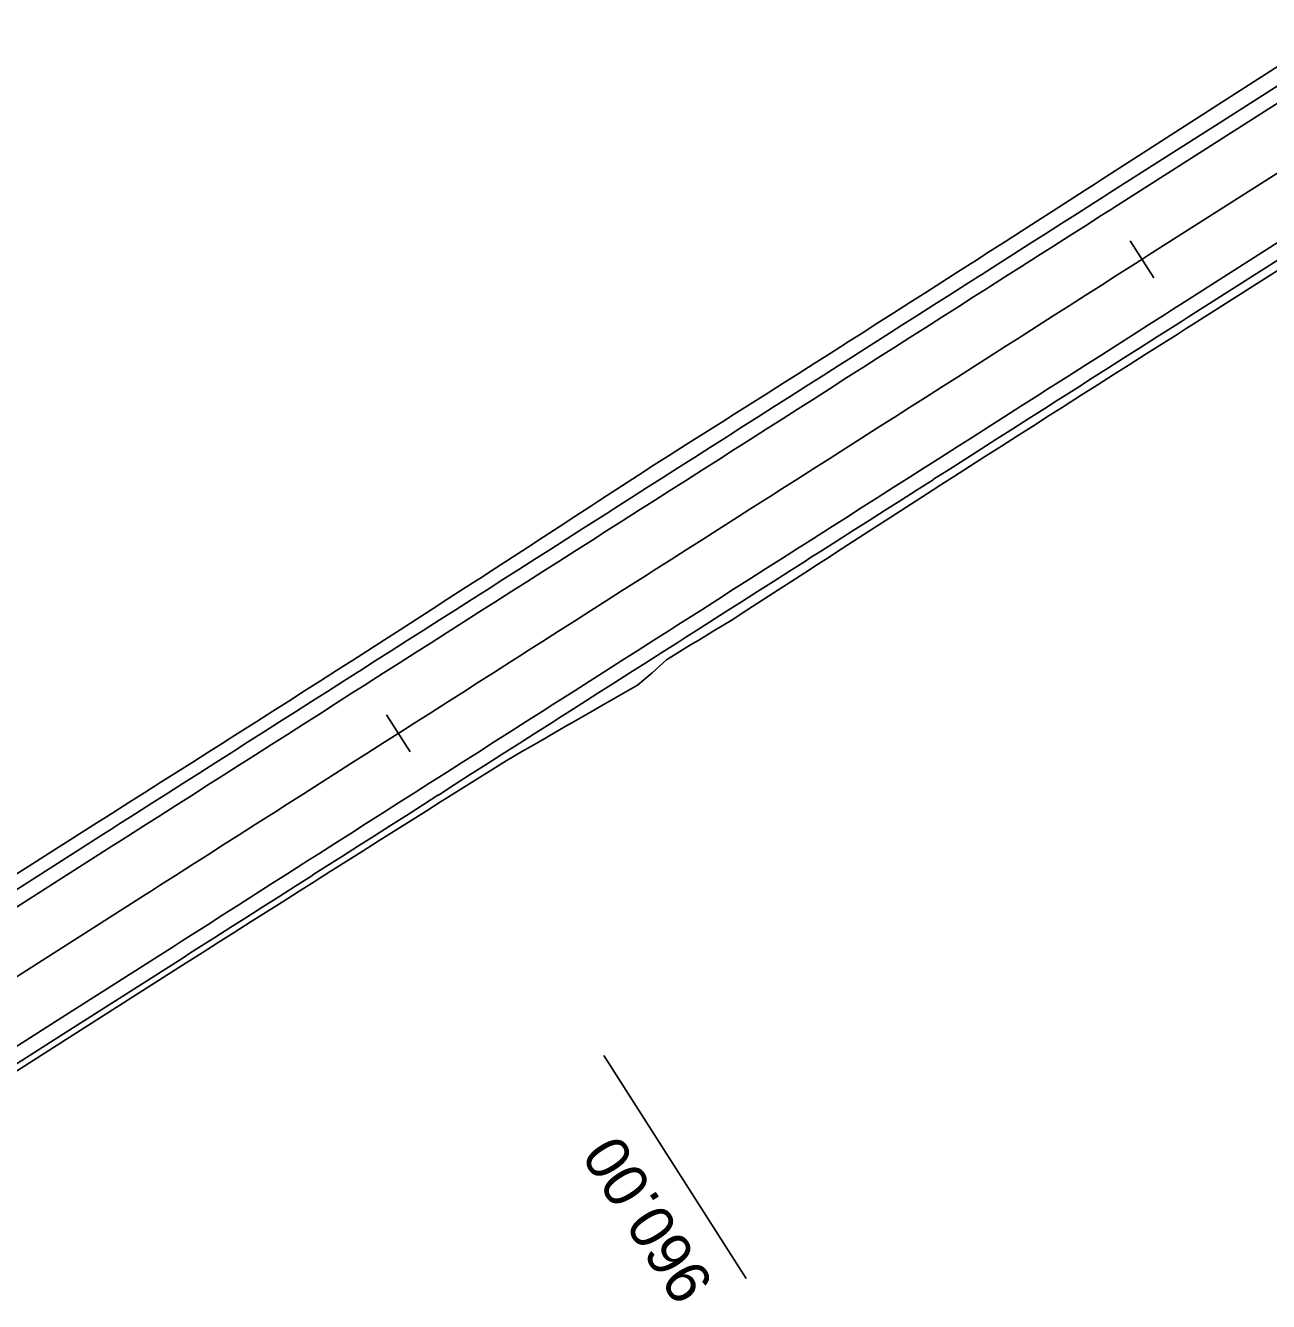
# Model space of a CAD drawing. Extents: x -550605 to -538780, y -1102367 to -1093705.
# Drawn here: x -547262.21 to -547219.93, y -1101213.61 to -1101170.2 of the extents above; entities that cross this region are included whole.
import ezdxf

# ---------------------------------------------------------------- set-up
doc = ezdxf.new("R2010")
doc.units = 0
for name, color, linetype in [('SIT - hrany vozovky', 7, 'Continuous'), ('SIT - osa cesty', 7, 'Continuous'), ('SIT - paty násypů', 7, 'Continuous'), ('SIT - staničení po 30m', 7, 'Continuous')]:
    doc.layers.add(name, color=color, linetype=linetype)

msp = doc.modelspace()

# ---------------------------------------------------------------- linework, layer by layer
at = {"layer": 'SIT - hrany vozovky'}
for points in [[(-547217.146, -1101170.672), (-547221.362, -1101173.36), (-547225.342, -1101175.897), (-547225.578, -1101176.048), (-547225.885, -1101176.243), (-547226.428, -1101176.589), (-547226.97, -1101176.935), (-547227.513, -1101177.282), (-547228.056, -1101177.628), (-547228.599, -1101177.974), (-547229.142, -1101178.32), (-547229.685, -1101178.666), (-547229.794, -1101178.735), (-547230.228, -1101179.012), (-547230.77, -1101179.358), (-547231.313, -1101179.704), (-547231.856, -1101180.05), (-547232.399, -1101180.396), (-547232.942, -1101180.743), (-547233.485, -1101181.089), (-547234.01, -1101181.423), (-547234.028, -1101181.435), (-547234.57, -1101181.781), (-547235.113, -1101182.127), (-547235.656, -1101182.473), (-547236.199, -1101182.819), (-547236.742, -1101183.165), (-547237.285, -1101183.511), (-547237.828, -1101183.857), (-547238.226, -1101184.111), (-547238.37, -1101184.204), (-547238.913, -1101184.55), (-547239.456, -1101184.896), (-547239.999, -1101185.242), (-547240.542, -1101185.588), (-547241.085, -1101185.934), (-547241.628, -1101186.28), (-547242.17, -1101186.626), (-547242.442, -1101186.799), (-547242.713, -1101186.972), (-547243.256, -1101187.318), (-547243.799, -1101187.665), (-547244.342, -1101188.011), (-547244.885, -1101188.357), (-547245.428, -1101188.703), (-547245.97, -1101189.049), (-547246.513, -1101189.395), (-547246.658, -1101189.487), (-547247.056, -1101189.741), (-547247.599, -1101190.087), (-547248.142, -1101190.433), (-547248.685, -1101190.779), (-547249.228, -1101191.126), (-547249.77, -1101191.472), (-547250.313, -1101191.818), (-547250.856, -1101192.164), (-547250.874, -1101192.175), (-547251.399, -1101192.51), (-547251.942, -1101192.856), (-547252.485, -1101193.202), (-547253.028, -1101193.548), (-547253.57, -1101193.894), (-547254.113, -1101194.24), (-547254.656, -1101194.587), (-547255.09, -1101194.863), (-547255.199, -1101194.933), (-547255.742, -1101195.279), (-547256.285, -1101195.625), (-547256.828, -1101195.971), (-547257.37, -1101196.317), (-547257.913, -1101196.663), (-547258.456, -1101197.009), (-547258.999, -1101197.355), (-547259.306, -1101197.551), (-547259.542, -1101197.701), (-547263.522, -1101200.239)], [(-547216.877, -1101171.093), (-547221.093, -1101173.781), (-547225.073, -1101176.319), (-547225.309, -1101176.469), (-547225.616, -1101176.665), (-547226.159, -1101177.011), (-547226.702, -1101177.357), (-547227.245, -1101177.703), (-547227.787, -1101178.049), (-547228.33, -1101178.395), (-547228.873, -1101178.741), (-547229.416, -1101179.088), (-547229.525, -1101179.157), (-547229.959, -1101179.434), (-547230.502, -1101179.78), (-547231.045, -1101180.126), (-547231.587, -1101180.472), (-547232.13, -1101180.818), (-547232.673, -1101181.164), (-547233.216, -1101181.51), (-547233.741, -1101181.845), (-547233.759, -1101181.856), (-547234.302, -1101182.202), (-547234.845, -1101182.549), (-547235.387, -1101182.895), (-547235.93, -1101183.241), (-547236.473, -1101183.587), (-547237.016, -1101183.933), (-547237.559, -1101184.279), (-547237.957, -1101184.533), (-547238.102, -1101184.625), (-547238.644, -1101184.971), (-547239.187, -1101185.317), (-547239.73, -1101185.663), (-547240.273, -1101186.01), (-547240.816, -1101186.356), (-547241.359, -1101186.702), (-547241.902, -1101187.048), (-547242.173, -1101187.221), (-547242.444, -1101187.394), (-547242.987, -1101187.74), (-547243.53, -1101188.086), (-547244.073, -1101188.432), (-547244.616, -1101188.778), (-547245.159, -1101189.124), (-547245.702, -1101189.471), (-547246.244, -1101189.817), (-547246.389, -1101189.909), (-547246.787, -1101190.163), (-547247.33, -1101190.509), (-547247.873, -1101190.855), (-547248.416, -1101191.201), (-547248.959, -1101191.547), (-547249.502, -1101191.893), (-547250.044, -1101192.239), (-547250.587, -1101192.585), (-547250.605, -1101192.597), (-547251.13, -1101192.932), (-547251.673, -1101193.278), (-547252.216, -1101193.624), (-547252.759, -1101193.97), (-547253.302, -1101194.316), (-547253.844, -1101194.662), (-547254.387, -1101195.008), (-547254.821, -1101195.285), (-547254.93, -1101195.354), (-547255.473, -1101195.7), (-547256.016, -1101196.046), (-547256.559, -1101196.393), (-547257.102, -1101196.739), (-547257.644, -1101197.085), (-547258.187, -1101197.431), (-547258.73, -1101197.777), (-547259.037, -1101197.973), (-547259.273, -1101198.123), (-547263.253, -1101200.661)], [(-547218.943, -1101177.154), (-547222.923, -1101179.692), (-547223.159, -1101179.842), (-547223.466, -1101180.038), (-547224.008, -1101180.384), (-547224.551, -1101180.73), (-547225.094, -1101181.076), (-547225.637, -1101181.422), (-547226.18, -1101181.768), (-547226.723, -1101182.114), (-547227.266, -1101182.46), (-547227.375, -1101182.53), (-547227.808, -1101182.806), (-547228.351, -1101183.153), (-547228.894, -1101183.499), (-547229.437, -1101183.845), (-547229.98, -1101184.191), (-547230.523, -1101184.537), (-547231.066, -1101184.883), (-547231.591, -1101185.218), (-547231.608, -1101185.229), (-547232.151, -1101185.575), (-547232.694, -1101185.921), (-547233.237, -1101186.267), (-547233.78, -1101186.614), (-547234.323, -1101186.96), (-547234.866, -1101187.306), (-547235.408, -1101187.652), (-547235.807, -1101187.906), (-547235.951, -1101187.998), (-547236.494, -1101188.344), (-547237.037, -1101188.69), (-547237.58, -1101189.036), (-547238.123, -1101189.382), (-547238.666, -1101189.728), (-547239.208, -1101190.075), (-547239.751, -1101190.421), (-547240.023, -1101190.594), (-547240.294, -1101190.767), (-547240.837, -1101191.113), (-547241.38, -1101191.459), (-547241.923, -1101191.805), (-547242.466, -1101192.151), (-547243.008, -1101192.497), (-547243.551, -1101192.843), (-547244.094, -1101193.189), (-547244.239, -1101193.282), (-547244.637, -1101193.536), (-547245.18, -1101193.882), (-547245.723, -1101194.228), (-547246.266, -1101194.574), (-547246.808, -1101194.92), (-547247.351, -1101195.266), (-547247.894, -1101195.612), (-547248.437, -1101195.958), (-547248.455, -1101195.97), (-547248.98, -1101196.304), (-547249.523, -1101196.651), (-547250.066, -1101196.997), (-547250.608, -1101197.343), (-547251.151, -1101197.689), (-547251.694, -1101198.035), (-547252.237, -1101198.381), (-547252.671, -1101198.658), (-547252.78, -1101198.727), (-547253.323, -1101199.073), (-547253.866, -1101199.419), (-547254.408, -1101199.765), (-547254.951, -1101200.112), (-547255.494, -1101200.458), (-547256.037, -1101200.804), (-547256.58, -1101201.15), (-547256.887, -1101201.346), (-547257.123, -1101201.496), (-547261.103, -1101204.033), (-547265.319, -1101206.721)], [(-547218.674, -1101177.576), (-547222.654, -1101180.113), (-547222.89, -1101180.264), (-547223.197, -1101180.459), (-547223.74, -1101180.805), (-547224.282, -1101181.151), (-547224.825, -1101181.498), (-547225.368, -1101181.844), (-547225.911, -1101182.19), (-547226.454, -1101182.536), (-547226.997, -1101182.882), (-547227.106, -1101182.951), (-547227.54, -1101183.228), (-547228.082, -1101183.574), (-547228.625, -1101183.92), (-547229.168, -1101184.266), (-547229.711, -1101184.612), (-547230.254, -1101184.959), (-547230.797, -1101185.305), (-547231.322, -1101185.639), (-547231.34, -1101185.651), (-547231.882, -1101185.997), (-547232.425, -1101186.343), (-547232.968, -1101186.689), (-547233.511, -1101187.035), (-547234.054, -1101187.381), (-547234.597, -1101187.727), (-547235.14, -1101188.073), (-547235.538, -1101188.327), (-547235.682, -1101188.42), (-547236.225, -1101188.766), (-547236.768, -1101189.112), (-547237.311, -1101189.458), (-547237.854, -1101189.804), (-547238.397, -1101190.15), (-547238.94, -1101190.496), (-547239.482, -1101190.842), (-547239.754, -1101191.015), (-547240.025, -1101191.188), (-547240.568, -1101191.534), (-547241.111, -1101191.881), (-547241.654, -1101192.227), (-547242.197, -1101192.573), (-547242.74, -1101192.919), (-547243.282, -1101193.265), (-547243.825, -1101193.611), (-547243.97, -1101193.703), (-547244.368, -1101193.957), (-547244.911, -1101194.303), (-547245.454, -1101194.649), (-547245.997, -1101194.996), (-547246.54, -1101195.342), (-547247.082, -1101195.688), (-547247.625, -1101196.034), (-547248.168, -1101196.38), (-547248.186, -1101196.391), (-547248.711, -1101196.726), (-547249.254, -1101197.072), (-547249.797, -1101197.418), (-547250.34, -1101197.764), (-547250.882, -1101198.11), (-547251.425, -1101198.457), (-547251.968, -1101198.803), (-547252.402, -1101199.079), (-547252.511, -1101199.149), (-547253.054, -1101199.495), (-547253.597, -1101199.841), (-547254.14, -1101200.187), (-547254.682, -1101200.533), (-547255.225, -1101200.879), (-547255.768, -1101201.225), (-547256.311, -1101201.571), (-547256.618, -1101201.767), (-547256.854, -1101201.918), (-547260.834, -1101204.455), (-547265.05, -1101207.143)]]:
    msp.add_lwpolyline(points, dxfattribs=at)
at = {"layer": 'SIT - osa cesty'}
msp.add_lwpolyline([(-547215.802, -1101172.78), (-547220.018, -1101175.468), (-547223.998, -1101178.005), (-547224.234, -1101178.156), (-547224.541, -1101178.351), (-547225.084, -1101178.697), (-547225.626, -1101179.043), (-547226.169, -1101179.39), (-547226.712, -1101179.736), (-547227.255, -1101180.082), (-547227.798, -1101180.428), (-547228.341, -1101180.774), (-547228.45, -1101180.843), (-547228.884, -1101181.12), (-547229.426, -1101181.466), (-547229.969, -1101181.812), (-547230.512, -1101182.158), (-547231.055, -1101182.504), (-547231.598, -1101182.851), (-547232.141, -1101183.197), (-547232.666, -1101183.531), (-547232.684, -1101183.543), (-547233.226, -1101183.889), (-547233.769, -1101184.235), (-547234.312, -1101184.581), (-547234.855, -1101184.927), (-547235.398, -1101185.273), (-547235.941, -1101185.619), (-547236.484, -1101185.965), (-547236.882, -1101186.219), (-547237.026, -1101186.312), (-547237.569, -1101186.658), (-547238.112, -1101187.004), (-547238.655, -1101187.35), (-547239.198, -1101187.696), (-547239.741, -1101188.042), (-547240.284, -1101188.388), (-547240.826, -1101188.734), (-547241.098, -1101188.907), (-547241.369, -1101189.08), (-547241.912, -1101189.426), (-547242.455, -1101189.773), (-547242.998, -1101190.119), (-547243.541, -1101190.465), (-547244.084, -1101190.811), (-547244.626, -1101191.157), (-547245.169, -1101191.503), (-547245.314, -1101191.595), (-547245.712, -1101191.849), (-547246.255, -1101192.195), (-547246.798, -1101192.541), (-547247.341, -1101192.887), (-547247.884, -1101193.234), (-547248.426, -1101193.58), (-547248.969, -1101193.926), (-547249.512, -1101194.272), (-547249.53, -1101194.283), (-547250.055, -1101194.618), (-547250.598, -1101194.964), (-547251.141, -1101195.31), (-547251.684, -1101195.656), (-547252.226, -1101196.002), (-547252.769, -1101196.348), (-547253.312, -1101196.695), (-547253.746, -1101196.971), (-547253.855, -1101197.041), (-547254.398, -1101197.387), (-547254.941, -1101197.733), (-547255.484, -1101198.079), (-547256.026, -1101198.425), (-547256.569, -1101198.771), (-547257.112, -1101199.117), (-547257.655, -1101199.463), (-547257.962, -1101199.659), (-547258.198, -1101199.81), (-547262.178, -1101202.347), (-547266.394, -1101205.035)], dxfattribs=at)
at = {"layer": 'SIT - paty násypů'}
for points in [[(-547217.447, -1101170.199), (-547221.654, -1101172.901), (-547225.625, -1101175.454), (-547225.86, -1101175.605), (-547226.166, -1101175.802), (-547226.707, -1101176.151), (-547227.249, -1101176.499), (-547227.79, -1101176.847), (-547228.332, -1101177.195), (-547228.874, -1101177.543), (-547229.416, -1101177.89), (-547229.958, -1101178.237), (-547230.067, -1101178.307), (-547230.5, -1101178.585), (-547231.042, -1101178.932), (-547231.585, -1101179.278), (-547232.127, -1101179.625), (-547232.67, -1101179.971), (-547233.213, -1101180.318), (-547233.756, -1101180.664), (-547234.281, -1101180.998), (-547234.299, -1101181.01), (-547234.842, -1101181.355), (-547235.385, -1101181.701), (-547235.928, -1101182.046), (-547236.472, -1101182.392), (-547237.015, -1101182.737), (-547237.559, -1101183.081), (-547238.103, -1101183.426), (-547238.502, -1101183.679), (-547238.647, -1101183.77), (-547239.191, -1101184.115), (-547239.735, -1101184.459), (-547240.279, -1101184.803), (-547240.822, -1101185.148), (-547241.362, -1101185.499), (-547241.903, -1101185.849), (-547242.443, -1101186.199), (-547242.713, -1101186.373), (-547242.984, -1101186.548), (-547243.522, -1101186.901), (-547244.059, -1101187.257), (-547244.599, -1101187.607), (-547245.139, -1101187.958), (-547245.679, -1101188.308), (-547246.219, -1101188.659), (-547246.76, -1101189.009), (-547246.904, -1101189.102), (-547247.3, -1101189.358), (-547247.841, -1101189.708), (-547248.382, -1101190.057), (-547248.922, -1101190.407), (-547249.463, -1101190.756), (-547250.004, -1101191.105), (-547250.546, -1101191.453), (-547251.089, -1101191.799), (-547251.106, -1101191.811), (-547251.631, -1101192.146), (-547252.174, -1101192.492), (-547252.717, -1101192.837), (-547253.26, -1101193.183), (-547253.804, -1101193.529), (-547254.347, -1101193.874), (-547254.89, -1101194.22), (-547255.323, -1101194.497), (-547255.433, -1101194.566), (-547255.976, -1101194.912), (-547256.519, -1101195.258), (-547257.062, -1101195.603), (-547257.605, -1101195.948), (-547258.149, -1101196.293), (-547258.693, -1101196.638), (-547259.236, -1101196.983), (-547259.544, -1101197.178), (-547259.78, -1101197.328), (-547263.768, -1101199.853)], [(-547218.509, -1101177.834), (-547222.496, -1101180.361), (-547222.732, -1101180.511), (-547223.039, -1101180.706), (-547223.583, -1101181.051), (-547224.127, -1101181.396), (-547224.67, -1101181.741), (-547225.213, -1101182.087), (-547225.757, -1101182.432), (-547226.3, -1101182.778), (-547226.843, -1101183.124), (-547226.952, -1101183.193), (-547227.386, -1101183.47), (-547227.928, -1101183.816), (-547228.471, -1101184.162), (-547229.014, -1101184.509), (-547229.556, -1101184.855), (-547230.098, -1101185.203), (-547230.64, -1101185.551), (-547231.164, -1101185.888), (-547231.181, -1101185.899), (-547231.723, -1101186.248), (-547232.264, -1101186.596), (-547232.805, -1101186.945), (-547233.346, -1101187.294), (-547233.887, -1101187.644), (-547234.427, -1101187.993), (-547234.968, -1101188.342), (-547235.365, -1101188.599), (-547235.509, -1101188.692), (-547236.049, -1101189.042), (-547236.59, -1101189.392), (-547237.13, -1101189.742), (-547237.67, -1101190.093), (-547238.213, -1101190.439), (-547238.763, -1101190.773), (-547239.313, -1101191.108), (-547239.588, -1101191.275), (-547239.863, -1101191.442), (-547240.413, -1101191.777), (-547240.893, -1101192.223), (-547241.391, -1101192.64), (-547241.95, -1101192.96), (-547242.509, -1101193.281), (-547243.068, -1101193.602), (-547243.626, -1101193.923), (-547243.775, -1101194.009), (-547244.185, -1101194.245), (-547244.743, -1101194.567), (-547245.301, -1101194.889), (-547245.859, -1101195.212), (-547246.404, -1101195.554), (-547246.949, -1101195.897), (-547247.494, -1101196.24), (-547248.039, -1101196.582), (-547248.057, -1101196.594), (-547248.584, -1101196.925), (-547249.129, -1101197.269), (-547249.673, -1101197.612), (-547250.218, -1101197.955), (-547250.762, -1101198.299), (-547251.306, -1101198.643), (-547251.85, -1101198.987), (-547252.285, -1101199.262), (-547252.394, -1101199.332), (-547252.938, -1101199.676), (-547253.482, -1101200.021), (-547254.026, -1101200.365), (-547254.569, -1101200.71), (-547255.113, -1101201.056), (-547255.656, -1101201.401), (-547256.199, -1101201.747), (-547256.506, -1101201.942), (-547256.742, -1101202.092), (-547260.724, -1101204.628), (-547264.941, -1101207.314)]]:
    msp.add_lwpolyline(points, dxfattribs=at)
at = {"layer": 'SIT - staničení po 30m'}
for points in [[(-547223.831, -1101178.788), (-547224.637, -1101177.523)], [(-547249.127, -1101194.916), (-547249.933, -1101193.651)], [(-547237.703, -1101212.834), (-547242.541, -1101205.245)]]:
    msp.add_lwpolyline(points, dxfattribs=at)

# ---------------------------------------------------------------- texts
msp.add_text('960.00', height=1.5, rotation=122.5198, dxfattribs=at).set_placement((-547238.771, -1101213.018))

doc.saveas('drawing.dxf')
